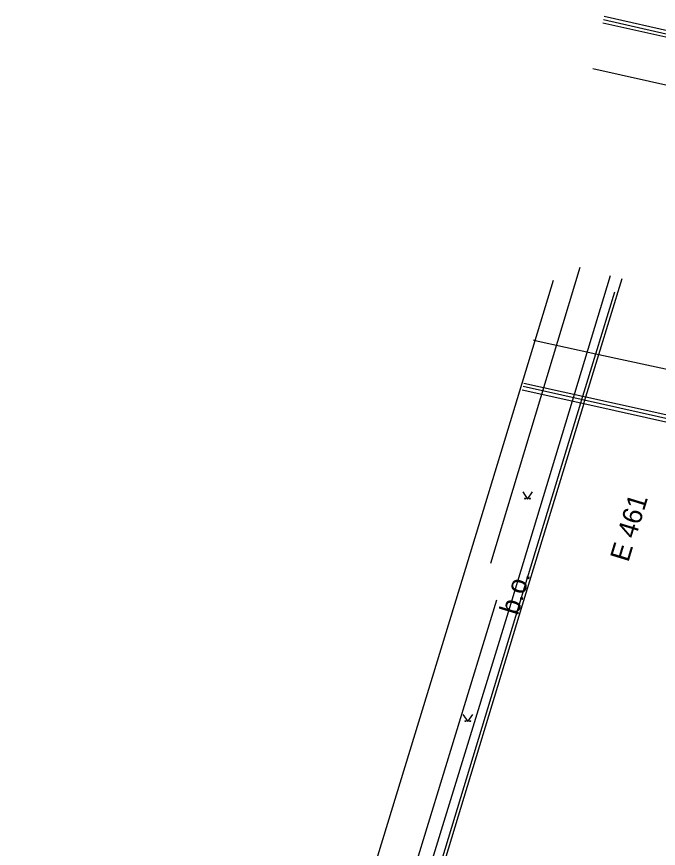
# Model space of a CAD drawing. Extents: x -601602 to -600882, y -1162594 to -1161950.
# Drawn here: x -601602.42 to -601569.41, y -1162301.67 to -1162258.87 of the extents above; entities that cross this region are included whole.
import ezdxf

# ---------------------------------------------------------------- set-up
doc = ezdxf.new("R2010")
doc.units = 0
for name, color, linetype in [('Vrstva 13', 7, 'Continuous'), ('Vrstva 16', 7, 'Continuous'), ('VRSTVA 3', 7, 'Continuous'), ('Vrstva 8', 7, 'Continuous')]:
    doc.layers.add(name, color=color, linetype=linetype)

msp = doc.modelspace()

# ---------------------------------------------------------------- linework, layer by layer
at = {"layer": 'Vrstva 13'}
for p, q in [((-601556.58, -1162262.75), (-601572.268, -1162259.201)), ((-601556.07, -1162262.52), (-601572.196, -1162258.872)), ((-601556.85, -1162265.11), (-601572.784, -1162261.553)), ((-601575.75, -1162275.53), (-601574.81, -1162272.43)), ((-601572.47, -1162276.25), (-601571.277, -1162272.339)), ((-601572.62, -1162276.22), (-601571.65, -1162273.03)), ((-601579.44, -1162287.64), (-601575.75, -1162275.53)), ((-601575.847, -1162275.508), (-601575.75, -1162275.53)), ((-601575.75, -1162275.53), (-601572.62, -1162276.22)), ((-601573.29, -1162278.4), (-601572.62, -1162276.22)), ((-601573.14, -1162278.43), (-601572.47, -1162276.25)), ((-601572.62, -1162276.22), (-601572.47, -1162276.25)), ((-601572.47, -1162276.25), (-601561.62, -1162278.63)), ((-601576.334, -1162277.728), (-601573.29, -1162278.4)), ((-601576.411, -1162278.08), (-601573.4, -1162278.75)), ((-601573.4, -1162278.75), (-601573.29, -1162278.4)), ((-601573.29, -1162278.4), (-601573.14, -1162278.43)), ((-601573.243, -1162278.779), (-601573.14, -1162278.43)), ((-601573.14, -1162278.43), (-601562.06, -1162280.9)), ((-601573.24, -1162278.78), (-601576.41, -1162289.16)), ((-601576.28, -1162288.19), (-601573.4, -1162278.75)), ((-601573.4, -1162278.75), (-601573.24, -1162278.78)), ((-601573.244, -1162278.784), (-601573.24, -1162278.78)), ((-601573.24, -1162278.78), (-601562.19, -1162281.24)), ((-601602.424, -1162362.969), (-601579.44, -1162287.64)), ((-601599.105, -1162363.472), (-601576.28, -1162288.19)), ((-601576.41, -1162289.16), (-601581.25, -1162305.05))]:
    msp.add_line(p, q, dxfattribs=at)
at = {"layer": 'VRSTVA 3'}
for points in [[(-601576.389, -1162283.323), (-601576.139, -1162283.698), (-601575.889, -1162283.323)], [(-601579.46, -1162294.773), (-601579.21, -1162295.148), (-601578.96, -1162294.773)]]:
    msp.add_lwpolyline(points, dxfattribs=at)
for centre in [(-601576.264, -1162283.673), (-601576.014, -1162283.673), (-601579.335, -1162295.123), (-601579.085, -1162295.123)]:
    msp.add_circle(centre, 0.025, dxfattribs=at)
at = {"layer": 'Vrstva 8'}
for p, q in [((-601556.12, -1162262.69), (-601572.234, -1162259.045)), ((-601573.449, -1162271.782), (-601578.04, -1162287.01)), ((-601576.98, -1162289.05), (-601571.87, -1162272.187)), ((-601576.37, -1162277.894), (-601562.12, -1162281.06)), ((-601582.43, -1162304.26), (-601577.72, -1162288.88)), ((-601581.81, -1162304.76), (-601576.98, -1162289.05))]:
    msp.add_line(p, q, dxfattribs=at)

# ---------------------------------------------------------------- texts
at = {"layer": 'Vrstva 16'}
for s, rotation, p in [('E 461', 73.0395, (-601570.957, -1162286.98)), ('b.o.', 73.0345, (-601576.639, -1162289.717))]:
    msp.add_text(s, height=1, rotation=rotation, dxfattribs=at).set_placement(p)

doc.saveas('drawing.dxf')
